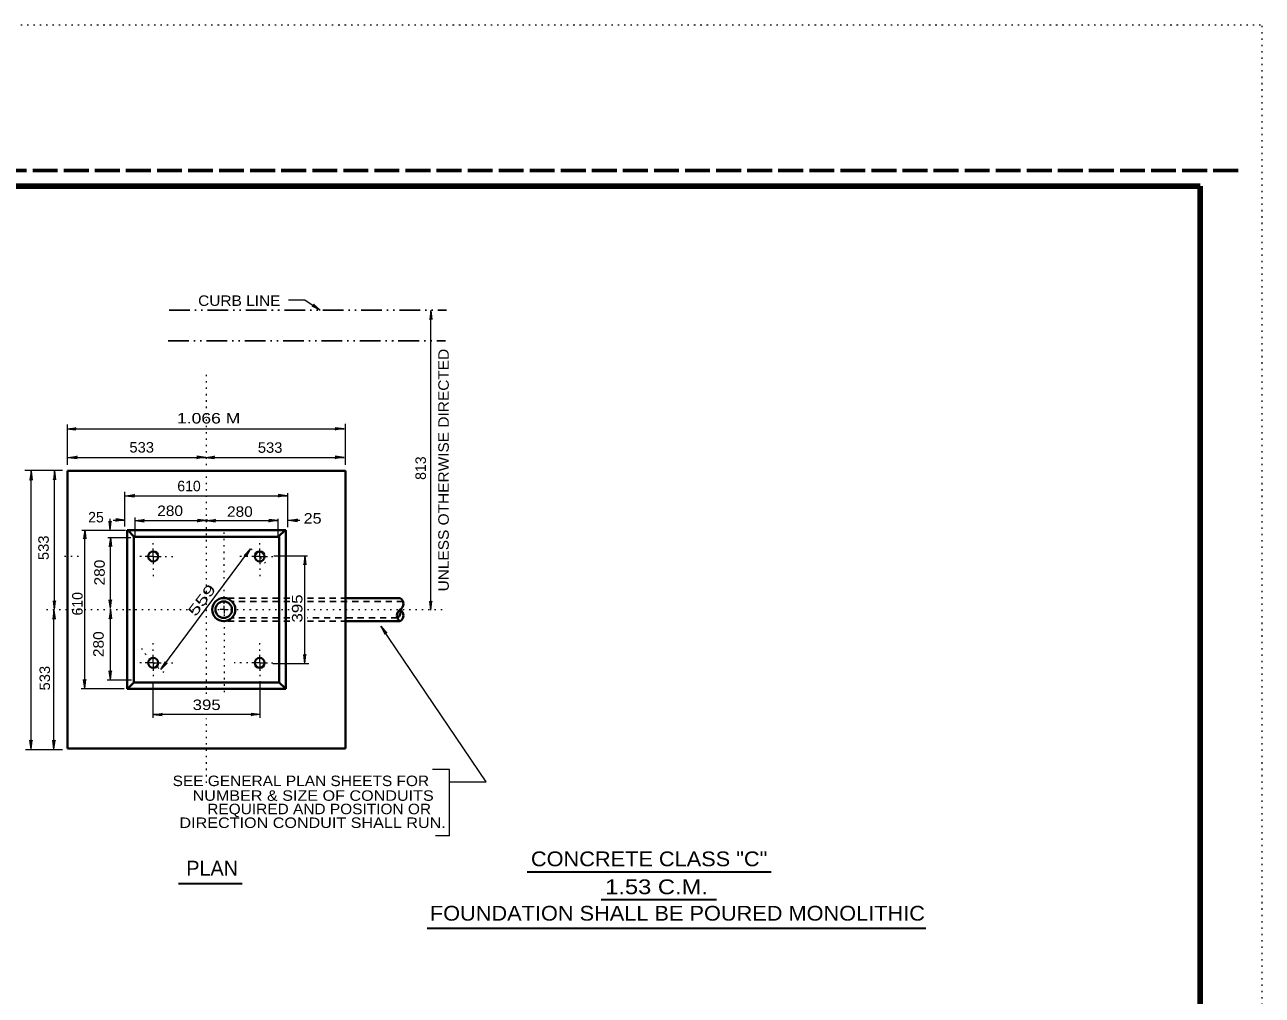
# Model space of a CAD drawing. Extents: x 312583 to 312854, y 144419 to 144597.
# Drawn here: x 312763.9 to 312853.5, y 144526.5 to 144596.8 of the extents above; entities that cross this region are included whole.
import ezdxf
from ezdxf.enums import TextEntityAlignment as Align

# ---------------------------------------------------------------- set-up
doc = ezdxf.new("R2010")
doc.units = 0
doc.header["$LTSCALE"] = 0.3
doc.header["$PDMODE"] = 32
doc.header["$PDSIZE"] = 0.15
for name, pattern in [('DASH_DOUBLE_DOT', [9.2, 5, -1.2, 0.3, -1.2, 0.3, -1.2]), ('DOTTED', [1.5, 0.3, -1.2]), ('LONG_DASHED', [7.5, 6, -1.5]), ('SHORT_DASHED', [2.7, 1.5, -1.2])]:
    doc.linetypes.add(name, pattern=pattern)
for name, color, linetype, lineweight in [('1', 7, 'Continuous', 25), ('2', 7, 'Continuous', 13), ('62', 7, 'DOTTED', 13), ('63', 7, 'LONG_DASHED', 60)]:
    doc.layers.add(name, color=color, linetype=linetype, lineweight=lineweight)

msp = doc.modelspace()

# ---------------------------------------------------------------- linework, layer by layer
at = {"layer": '1', "lineweight": 158}
msp.add_line((312849, 144423.1446), (312849, 144585.0846), dxfattribs=at)
at = {"layer": '1', "lineweight": 40}
for p, q in [((312766.9716, 144564.466), (312766.9716, 144544.341)), ((312787.0966, 144564.466), (312766.9716, 144564.466)), ((312787.0966, 144564.466), (312787.0966, 144544.341)), ((312771.2803, 144560.1573), (312771.2803, 144548.6573)), ((312782.7803, 144560.1573), (312771.2803, 144560.1573)), ((312771.8016, 144559.6743), (312771.3263, 144560.1573)), ((312771.7633, 144559.6743), (312771.7633, 144549.1326)), ((312782.3049, 144559.6743), (312771.7633, 144559.6743)), ((312782.7343, 144560.1726), (312782.2589, 144559.6973)), ((312782.3049, 144559.6743), (312782.3049, 144549.1326)), ((312782.7803, 144560.1573), (312782.7803, 144548.6573)), ((312791.0603, 144555.243), (312787.0966, 144555.243)), ((312791.0603, 144553.564), (312787.0966, 144553.564)), ((312782.7803, 144548.6573), (312771.2803, 144548.6573)), ((312771.7786, 144549.1326), (312771.3033, 144548.6573)), ((312782.3049, 144549.1326), (312771.7633, 144549.1326)), ((312782.7573, 144548.6803), (312782.2819, 144549.1556)), ((312787.0966, 144544.341), (312766.9716, 144544.341))]:
    msp.add_line(p, q, dxfattribs=at)
at = {"layer": '1', "linetype": 'SHORT_DASHED'}
for p, q in [((312783.076, 144555.243), (312778.5636, 144555.243)), ((312783.076, 144555.0053), (312778.9469, 144555.0053)), ((312788.0243, 144555.243), (312784.3519, 144555.243)), ((312791.2749, 144555.0053), (312784.3519, 144555.0053)), ((312783.076, 144553.564), (312778.5636, 144553.564)), ((312783.076, 144553.8093), (312778.9393, 144553.8093)), ((312790.8609, 144553.8093), (312784.3519, 144553.8093)), ((312788.0243, 144553.564), (312784.3519, 144553.564))]:
    msp.add_line(p, q, dxfattribs=at)
at = {"layer": '1', "lineweight": 35}
msp.add_line((312779.6069, 144534.5457), (312775.0092, 144534.5457), dxfattribs=at)
at = {"layer": '1', "lineweight": 158}
msp.add_lwpolyline([(312616.5, 144423.1446), (312616.5, 144585.0846), (312849, 144585.0846)], dxfattribs=at)
at = {"layer": '1', "lineweight": 40}
for centre, radius in [((312773.1744, 144558.2608), 0.3594), ((312780.8861, 144558.2608), 0.3594), ((312778.2814, 144554.4054), 0.8385), ((312778.2814, 144554.4054), 0.599), ((312773.1744, 144550.5491), 0.3594), ((312780.8861, 144550.5491), 0.3594)]:
    msp.add_circle(centre, radius, dxfattribs=at)
for centre, start, end in [((312790.8113, 144554.8242), 300.60313, 59.39687), ((312791.3073, 144553.9856), 120.60313, 239.39687), ((312790.6067, 144554.2252), 300.60313, 21.65707), ((312790.8113, 144553.9856), 300.60313, 59.39687)]:
    msp.add_arc(centre, 0.4871, start, end, dxfattribs=at)
at = {"layer": '2'}
for p, q in [((312784.6969, 144576.403), (312784.9116, 144576.3493)), ((312785.2719, 144576.0963), (312784.6969, 144576.403)), ((312784.7889, 144576.5333), (312784.9116, 144576.3493)), ((312785.2719, 144576.0963), (312784.7889, 144576.5333)), ((312793.2759, 144576.0886), (312793.1993, 144575.437)), ((312793.1993, 144575.437), (312793.2759, 144575.644)), ((312793.2759, 144554.3766), (312793.2759, 144576.0886)), ((312793.2759, 144576.0886), (312793.3603, 144575.437)), ((312793.3603, 144575.437), (312793.2759, 144575.644)), ((312766.9256, 144567.5096), (312767.5773, 144567.5863)), ((312766.9256, 144567.5096), (312787.0123, 144567.5096)), ((312766.9256, 144567.5096), (312767.5773, 144567.4253)), ((312766.9716, 144564.903), (312766.9716, 144567.824)), ((312767.5773, 144567.5863), (312767.3703, 144567.5096)), ((312767.5773, 144567.4253), (312767.3703, 144567.5096)), ((312786.3606, 144567.5863), (312786.5676, 144567.5096)), ((312787.0123, 144567.5096), (312786.3606, 144567.5863)), ((312786.3606, 144567.4253), (312786.5676, 144567.5096)), ((312787.0123, 144567.5096), (312786.3606, 144567.4253)), ((312787.0966, 144564.903), (312787.0966, 144567.8623)), ((312767.0099, 144565.4396), (312767.6616, 144565.524)), ((312767.0099, 144565.4396), (312776.9843, 144565.4396)), ((312767.0099, 144565.4396), (312767.6616, 144565.363)), ((312767.6616, 144565.524), (312767.4546, 144565.4396)), ((312767.6616, 144565.363), (312767.4546, 144565.4396)), ((312776.3326, 144565.524), (312776.5396, 144565.4396)), ((312776.9843, 144565.4396), (312776.3326, 144565.524)), ((312776.3326, 144565.363), (312776.5396, 144565.4396)), ((312776.9843, 144565.4396), (312776.3326, 144565.363)), ((312776.9613, 144565.4396), (312777.6129, 144565.524)), ((312776.9613, 144565.4396), (312787.0123, 144565.4396)), ((312776.9613, 144565.4396), (312777.6129, 144565.363)), ((312777.6129, 144565.524), (312777.4059, 144565.4396)), ((312777.6129, 144565.363), (312777.4059, 144565.4396)), ((312786.3606, 144565.524), (312786.5676, 144565.4396)), ((312787.0123, 144565.4396), (312786.3606, 144565.524)), ((312786.3606, 144565.363), (312786.5676, 144565.4396)), ((312787.0123, 144565.4396), (312786.3606, 144565.363)), ((312763.8819, 144564.5043), (312766.6113, 144564.5043)), ((312764.3343, 144564.4276), (312764.2499, 144563.776)), ((312764.2499, 144563.776), (312764.3343, 144563.983)), ((312764.3343, 144544.3026), (312764.3343, 144564.4276)), ((312764.3343, 144564.4276), (312764.4109, 144563.776)), ((312764.4109, 144563.776), (312764.3343, 144563.983)), ((312766.0286, 144564.466), (312765.9443, 144563.8143)), ((312765.9443, 144563.8143), (312766.0286, 144564.0213)), ((312766.0286, 144554.4073), (312766.0286, 144564.466)), ((312766.0286, 144564.466), (312766.1053, 144563.8143)), ((312766.1053, 144563.8143), (312766.0286, 144564.0213)), ((312771.1269, 144560.418), (312771.1269, 144562.9326)), ((312771.1729, 144562.6566), (312771.8169, 144562.741)), ((312771.1729, 144562.6566), (312782.8723, 144562.6566)), ((312771.1729, 144562.6566), (312771.8169, 144562.58)), ((312771.8169, 144562.741), (312771.6099, 144562.6566)), ((312771.8169, 144562.58), (312771.6099, 144562.6566)), ((312782.2206, 144562.741), (312782.4276, 144562.6566)), ((312782.8723, 144562.6566), (312782.2206, 144562.741)), ((312782.2206, 144562.58), (312782.4276, 144562.6566)), ((312782.8723, 144562.6566), (312782.2206, 144562.58)), ((312782.9183, 144560.3796), (312782.9183, 144562.8483)), ((312769.9769, 144560.809), (312770.0536, 144560.602)), ((312770.0536, 144560.1573), (312769.9769, 144560.809)), ((312770.0536, 144560.1573), (312770.0536, 144560.9853)), ((312770.1379, 144560.809), (312770.0536, 144560.602)), ((312770.0536, 144560.1573), (312770.1379, 144560.809)), ((312770.2836, 144560.8933), (312771.1116, 144560.8933)), ((312770.4599, 144560.9776), (312770.6669, 144560.8933)), ((312771.1116, 144560.8933), (312770.4599, 144560.9776)), ((312770.4599, 144560.8166), (312770.6669, 144560.8933)), ((312771.1116, 144560.8933), (312770.4599, 144560.8166)), ((312771.8706, 144559.7893), (312771.8706, 144561.0696)), ((312771.8706, 144560.855), (312772.5223, 144560.9316)), ((312771.8706, 144560.855), (312777.0226, 144560.855)), ((312771.8706, 144560.855), (312772.5223, 144560.7706)), ((312772.5223, 144560.9316), (312772.3153, 144560.855)), ((312772.5223, 144560.7706), (312772.3153, 144560.855)), ((312776.3786, 144560.9316), (312776.5856, 144560.855)), ((312777.0226, 144560.855), (312776.3786, 144560.9316)), ((312776.3786, 144560.7706), (312776.5856, 144560.855)), ((312777.0226, 144560.855), (312776.3786, 144560.7706)), ((312777.0303, 144560.855), (312777.6819, 144560.9316)), ((312777.0303, 144560.855), (312777.6819, 144560.9316)), ((312777.0303, 144560.855), (312782.1899, 144560.855)), ((312777.0303, 144560.855), (312777.6819, 144560.7706)), ((312777.0303, 144560.855), (312777.6819, 144560.7706)), ((312777.6819, 144560.9316), (312777.4749, 144560.855)), ((312777.6819, 144560.9316), (312777.4749, 144560.855)), ((312777.6819, 144560.7706), (312777.4749, 144560.855)), ((312777.6819, 144560.7706), (312777.4749, 144560.855)), ((312781.5459, 144560.9316), (312781.7529, 144560.855)), ((312782.1899, 144560.855), (312781.5459, 144560.9316)), ((312781.5459, 144560.7706), (312781.7529, 144560.855)), ((312782.1899, 144560.855), (312781.5459, 144560.7706)), ((312782.2359, 144559.7816), (312782.2359, 144560.9776)), ((312782.9719, 144560.878), (312783.6159, 144560.9546)), ((312782.9719, 144560.878), (312783.7923, 144560.878)), ((312782.9719, 144560.878), (312783.6159, 144560.7936)), ((312783.6159, 144560.9546), (312783.4089, 144560.878)), ((312783.6159, 144560.7936), (312783.4089, 144560.878)), ((312768.0143, 144560.1726), (312771.1653, 144560.1726)), ((312768.2213, 144560.1803), (312768.1369, 144559.5286)), ((312768.1369, 144559.5286), (312768.2213, 144559.7356)), ((312768.2213, 144548.688), (312768.2213, 144560.1803)), ((312768.2213, 144560.1803), (312768.2979, 144559.5286)), ((312768.2979, 144559.5286), (312768.2213, 144559.7356)), ((312769.8849, 144559.6206), (312771.5486, 144559.6206)), ((312770.0689, 144559.636), (312769.9846, 144558.9843)), ((312770.0689, 144554.484), (312770.0689, 144559.636)), ((312770.0689, 144559.636), (312770.1456, 144558.9843)), ((312769.9846, 144558.9843), (312770.0689, 144559.1913)), ((312770.1456, 144558.9843), (312770.0689, 144559.1913)), ((312773.1739, 144558.2636), (312773.1739, 144558.8386)), ((312773.7336, 144550.0603), (312780.2196, 144558.808)), ((312780.2196, 144558.808), (312779.7673, 144558.3326)), ((312780.2196, 144558.808), (312779.8976, 144558.2406)), ((312780.8866, 144558.2636), (312780.8866, 144558.8386)), ((312773.1739, 144558.2636), (312772.5989, 144558.2636)), ((312773.1739, 144558.2636), (312773.1739, 144557.6886)), ((312773.1739, 144558.2636), (312773.7489, 144558.2636)), ((312779.7673, 144558.3326), (312779.9589, 144558.4553)), ((312779.8976, 144558.2406), (312779.9589, 144558.4553)), ((312780.8866, 144558.2636), (312780.3116, 144558.2636)), ((312780.8866, 144558.2636), (312780.8866, 144557.6886)), ((312780.8866, 144558.2636), (312781.4616, 144558.2636)), ((312781.9216, 144558.302), (312784.3519, 144558.302)), ((312784.1603, 144558.302), (312784.0759, 144557.6503)), ((312784.0759, 144557.6503), (312784.1603, 144557.8573)), ((312784.1603, 144558.302), (312784.2369, 144557.6503)), ((312784.2369, 144557.6503), (312784.1603, 144557.8573)), ((312765.9443, 144555.0513), (312766.0286, 144554.8443)), ((312766.0286, 144554.4073), (312765.9443, 144555.0513)), ((312766.1053, 144555.0513), (312766.0286, 144554.8443)), ((312766.0286, 144554.4073), (312766.1053, 144555.0513)), ((312769.9846, 144555.128), (312770.0689, 144554.921)), ((312770.0689, 144554.484), (312769.9846, 144555.128)), ((312770.1456, 144555.128), (312770.0689, 144554.921)), ((312770.0689, 144554.484), (312770.1456, 144555.128)), ((312793.1993, 144555.0283), (312793.2759, 144554.8213)), ((312793.2759, 144554.3766), (312793.1993, 144555.0283)), ((312793.3603, 144555.0283), (312793.2759, 144554.8213)), ((312793.2759, 144554.3766), (312793.3603, 144555.0283)), ((312765.9826, 144554.3613), (312765.9059, 144553.7096)), ((312765.9826, 144544.3026), (312765.9826, 144554.3613)), ((312765.9826, 144554.3613), (312766.0669, 144553.7096)), ((312770.0689, 144554.3996), (312769.9846, 144553.748)), ((312770.0689, 144549.3243), (312770.0689, 144554.3996)), ((312770.0689, 144554.3996), (312770.1456, 144553.748)), ((312778.3106, 144554.4073), (312778.0193, 144554.4073)), ((312778.3106, 144554.4073), (312778.3106, 144554.691)), ((312778.3106, 144554.4073), (312778.3106, 144554.116)), ((312778.3106, 144554.4073), (312778.5943, 144554.4073)), ((312765.9059, 144553.7096), (312765.9826, 144553.9166)), ((312766.0669, 144553.7096), (312765.9826, 144553.9166)), ((312769.9846, 144553.748), (312770.0689, 144553.955)), ((312770.1456, 144553.748), (312770.0689, 144553.955)), ((312789.6573, 144553.2036), (312789.9563, 144552.621)), ((312789.6573, 144553.2036), (312790.0866, 144552.713)), ((312789.9563, 144552.621), (312789.9026, 144552.8356)), ((312790.0866, 144552.713), (312789.9026, 144552.8356)), ((312773.1739, 144550.551), (312772.5989, 144550.551)), ((312773.1739, 144550.551), (312773.1739, 144551.126)), ((312773.1739, 144550.551), (312773.1739, 144549.976)), ((312773.1739, 144550.551), (312773.7489, 144550.551)), ((312773.7336, 144550.0603), (312774.0556, 144550.6353)), ((312773.7336, 144550.0603), (312774.1783, 144550.5356)), ((312774.0556, 144550.6353), (312773.9943, 144550.4206)), ((312774.1783, 144550.5356), (312773.9943, 144550.4206)), ((312780.8866, 144550.551), (312780.3116, 144550.551)), ((312780.8866, 144550.551), (312780.8866, 144551.126)), ((312780.8866, 144550.551), (312780.8866, 144549.976)), ((312780.8866, 144550.551), (312781.4616, 144550.551)), ((312781.8373, 144550.5126), (312784.4439, 144550.5126)), ((312784.0759, 144551.1566), (312784.1603, 144550.9496)), ((312784.1603, 144550.5126), (312784.0759, 144551.1566)), ((312784.2369, 144551.1566), (312784.1603, 144550.9496)), ((312784.1603, 144550.5126), (312784.2369, 144551.1566)), ((312769.9846, 144549.976), (312770.0689, 144549.769)), ((312770.0689, 144549.3243), (312769.9846, 144549.976)), ((312770.1456, 144549.976), (312770.0689, 144549.769)), ((312770.0689, 144549.3243), (312770.1456, 144549.976)), ((312767.9683, 144548.6803), (312771.0809, 144548.6803)), ((312768.1369, 144549.3396), (312768.2213, 144549.1326)), ((312768.2213, 144548.688), (312768.1369, 144549.3396)), ((312768.2979, 144549.3396), (312768.2213, 144549.1326)), ((312768.2213, 144548.688), (312768.2979, 144549.3396)), ((312769.8466, 144549.3166), (312770.0689, 144549.3166)), ((312770.0766, 144549.3166), (312771.5946, 144549.3166)), ((312773.1739, 144546.5643), (312773.1739, 144549.1173)), ((312780.9173, 144546.5643), (312780.9173, 144549.2246)), ((312773.1739, 144546.8096), (312773.8179, 144546.8863)), ((312780.9173, 144546.8096), (312773.1739, 144546.8096)), ((312773.1739, 144546.8096), (312773.8179, 144546.7253)), ((312773.8179, 144546.8863), (312773.6109, 144546.8096)), ((312773.8179, 144546.7253), (312773.6109, 144546.8096)), ((312780.2656, 144546.8863), (312780.4726, 144546.8096)), ((312780.9173, 144546.8096), (312780.2656, 144546.8863)), ((312780.2656, 144546.7253), (312780.4726, 144546.8096)), ((312780.9173, 144546.8096), (312780.2656, 144546.7253)), ((312763.9279, 144544.2796), (312766.6113, 144544.2796)), ((312764.2499, 144544.9466), (312764.3343, 144544.7396)), ((312764.3343, 144544.3026), (312764.2499, 144544.9466)), ((312764.4109, 144544.9466), (312764.3343, 144544.7396)), ((312764.3343, 144544.3026), (312764.4109, 144544.9466)), ((312765.9059, 144544.9466), (312765.9826, 144544.7396)), ((312765.9826, 144544.3026), (312765.9059, 144544.9466)), ((312766.0669, 144544.9466), (312765.9826, 144544.7396)), ((312765.9826, 144544.3026), (312766.0669, 144544.9466)), ((312794.6406, 144538.0082), (312793.6133, 144538.0082))]:
    msp.add_line(p, q, dxfattribs=at)
at = {"layer": '2', "linetype": 'DASH_DOUBLE_DOT', "lineweight": 25}
for p, q in [((312774.3316, 144576.104), (312794.4183, 144576.104)), ((312774.2473, 144573.8883), (312794.3339, 144573.8883))]:
    msp.add_line(p, q, dxfattribs=at)
at = {"layer": '2', "linetype": 'DOTTED'}
for p, q in [((312777.0303, 144548.3123), (312777.0303, 144571.6496)), ((312773.1739, 144559.1223), (312773.1739, 144559.36)), ((312778.3029, 144554.829), (312778.3029, 144560.2263)), ((312780.8866, 144559.1223), (312780.8866, 144559.4903)), ((312767.7689, 144558.2636), (312766.5653, 144558.2636)), ((312772.3153, 144558.2636), (312771.9396, 144558.2636)), ((312774.0403, 144558.2636), (312774.7303, 144558.2636)), ((312780.0203, 144558.2636), (312779.3456, 144558.2636)), ((312781.7453, 144558.2636), (312782.1133, 144558.2636)), ((312773.1739, 144557.3973), (312773.1739, 144556.83)), ((312780.8866, 144557.3973), (312780.8866, 144556.807)), ((312765.4383, 144554.4073), (312783.076, 144554.4073)), ((312778.3029, 144554.0546), (312778.3029, 144548.297)), ((312784.3519, 144554.4073), (312794.4106, 144554.4073)), ((312773.1739, 144551.4096), (312773.1739, 144552.1226)), ((312780.8866, 144551.4096), (312780.8866, 144552)), ((312772.3153, 144550.551), (312771.9856, 144550.551)), ((312774.0403, 144550.551), (312774.7303, 144550.551)), ((312780.0203, 144550.551), (312779.0466, 144550.551)), ((312781.7453, 144550.551), (312782.0289, 144550.551)), ((312773.1739, 144549.6846), (312773.1739, 144549.3166)), ((312780.8866, 144549.6846), (312780.8866, 144549.3626)), ((312777.0303, 144541.8646), (312777.0303, 144546.526))]:
    msp.add_line(p, q, dxfattribs=at)
at = {"layer": '2', "lineweight": 35}
for p, q in [((312817.9315, 144535.3861), (312800.2589, 144535.3861)), ((312813.9803, 144533.3851), (312805.611, 144533.3851)), ((312829.1363, 144531.2998), (312793.0105, 144531.2998))]:
    msp.add_line(p, q, dxfattribs=at)
at = {"layer": '2'}
for points in [[(312782.9796, 144576.863), (312784.1679, 144576.863), (312785.2719, 144576.0963)], [(312784.1603, 144550.5126), (312784.1603, 144555.427), (312784.1603, 144558.302)], [(312794.6943, 144541.9183), (312797.2933, 144541.9183), (312789.6573, 144553.2036)], [(312794.6406, 144538.0082), (312794.6406, 144542.8304), (312793.3986, 144542.8304)]]:
    msp.add_lwpolyline(points, dxfattribs=at)
at = {"layer": '2', "linetype": 'DOTTED'}
for start, end in [(38.08146, 57.27506), (210.69582, 239.49146)]:
    msp.add_arc((312777.0183, 144554.3934), 5.4625, start, end, dxfattribs=at)
at = {"layer": '2'}
msp.add_point((312777.0303, 144560.855), dxfattribs=at)
at = {"layer": '62'}
msp.add_line((312601.2, 144596.7846), (312853.5, 144596.7846), dxfattribs=at)
msp.add_lwpolyline([(312601.2, 144418.5846), (312853.5, 144418.5846), (312853.5, 144596.7846)], dxfattribs=at)
at = {"layer": '63'}
msp.add_line((312851.75, 144586.2246), (312583.526, 144586.2246), dxfattribs=at)

# ---------------------------------------------------------------- texts
at = {"layer": '2'}
for s, width, p in [('CURB LINE', 1.1, (312776.4275, 144576.4127)), ('1.066 M', 1.25, (312774.8953, 144567.8926)), ('533', 1.05, (312771.4508, 144565.7867)), ('533', 1.05, (312780.753, 144565.7685)), ('280', 1.1, (312773.4661, 144561.1891)), ('280', 1.1, (312778.5202, 144561.1305)), ('25 ', 1.15, (312784.0708, 144560.6378)), ('395 ', 1.2, (312776.0279, 144547.1319)), ('SEE GENERAL PLAN SHEETS FOR', 1.1, (312774.5816, 144541.6193)), ('NUMBER & SIZE OF CONDUITS', 1.15, (312776.0246, 144540.5537)), ('REQUIRED AND POSITION OR', 1.1, (312777.088, 144539.5827)), ('DIRECTION CONDUIT SHALL RUN.', 1.15, (312775.0768, 144538.5854))]:
    msp.add_text(s, height=0.76, dxfattribs=dict(at, width=width)).set_placement(p)
for s, rotation, width, p in [('UNLESS OTHERWISE DIRECTED', 90, 1.1, (312794.5817, 144555.7266)), ('533', 90, 1.05, (312765.6097, 144557.9968)), ('280', 90, 1.1, (312769.6644, 144556.1589)), ('559 ', 53, 1.5, (312776.2352, 144553.851)), ('395 ', 90, 1.2, (312783.9824, 144553.4729)), ('280', 90, 1.1, (312769.59, 144550.9677)), ('533', 90, 1.05, (312765.7002, 144548.5505))]:
    msp.add_text(s, height=0.76, rotation=rotation, dxfattribs=dict(at, width=width)).set_placement(p)
for s, p in [('813', (312792.9265, 144563.8084)), ('610', (312768.0612, 144553.9833))]:
    msp.add_text(s, height=0.76, rotation=90, dxfattribs=at).set_placement(p)
for s, p in [('610', (312774.9201, 144562.9807)), ('25', (312768.4641, 144560.727))]:
    msp.add_text(s, height=0.76, dxfattribs=at).set_placement(p)
msp.add_text('PLAN', height=1.07, dxfattribs=at).set_placement((312777.4427, 144535.1404), align=Align.CENTER)
for s, width, p in [('CONCRETE CLASS "C"', 1.1, (312809.0942, 144535.8133)), ('1.53 C.M.', 1.2, (312809.6299, 144533.7893)), ('FOUNDATION SHALL BE POURED MONOLITHIC', 1.1, (312811.1419, 144531.8726))]:
    msp.add_text(s, height=1.07, dxfattribs=dict(at, width=width)).set_placement(p, align=Align.CENTER)

doc.saveas('drawing.dxf')
